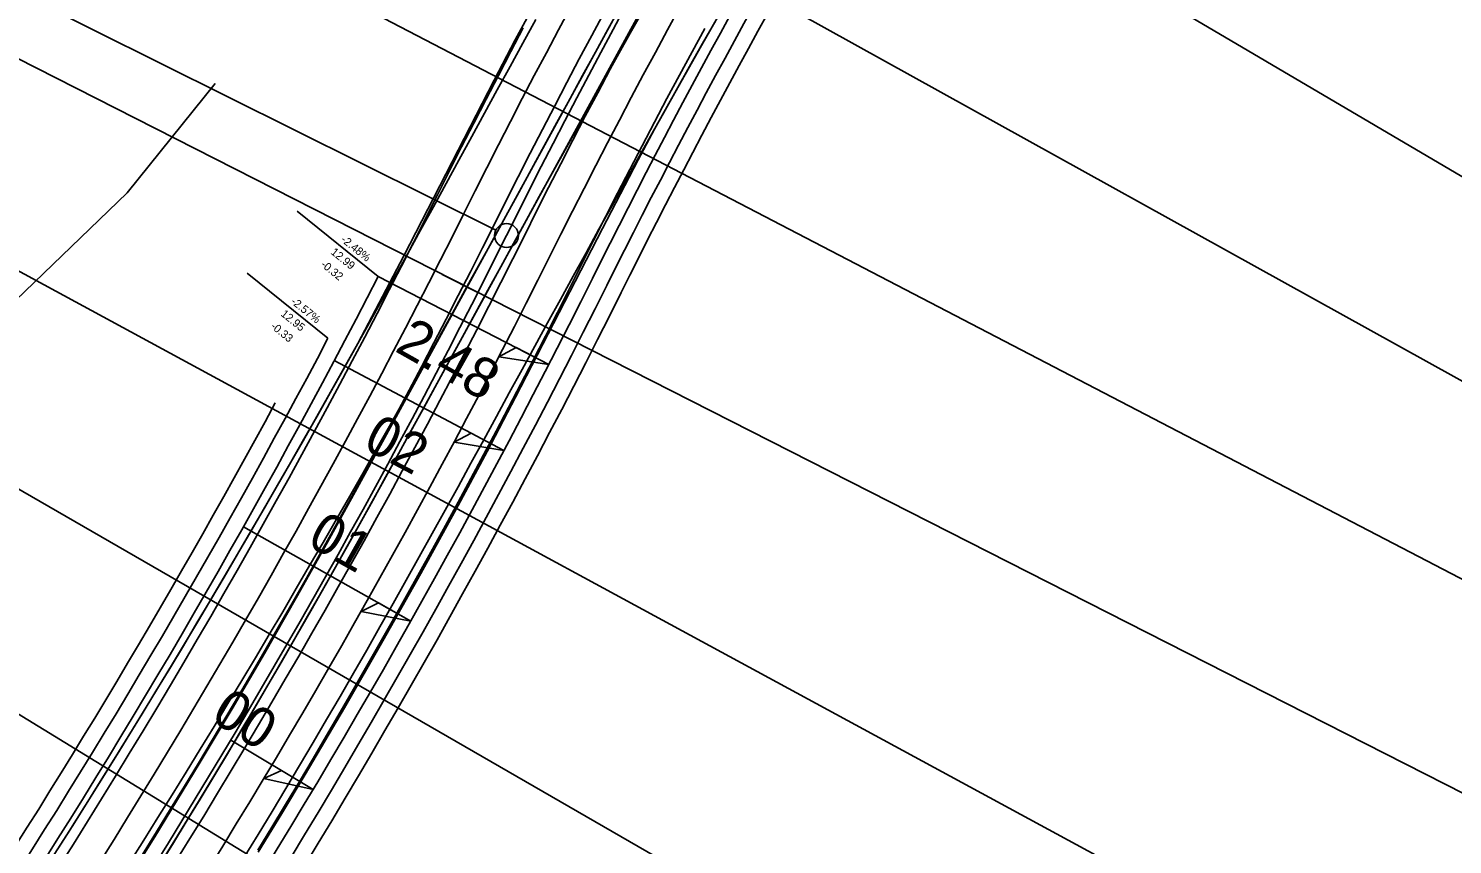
# Model space of a CAD drawing. Extents: x 2293233 to 2294507, y 892788 to 894229.
# Drawn here: x 2294121.5 to 2294299.4, y 893806.4 to 893908.4 of the extents above; entities that cross this region are included whole.
import ezdxf

# ---------------------------------------------------------------- set-up
doc = ezdxf.new("R2010")
doc.units = 0
for name, color, linetype in [('COGO Default Curve', 7, 'Continuous'), ('Default', 7, 'Continuous'), ('Prop EOT', 7, 'Continuous'), ('Prop Horizontal Alignment', 7, 'Continuous'), ('Prop Paved Shoulder', 7, 'Continuous'), ('Prop Superelevation  Arrow CELL', 7, 'Continuous'), ('Prop Superelevation Label', 7, 'Continuous'), ('Scratch_Level_0', 7, 'Continuous'), ('Scratch_Level_4', 7, 'Continuous'), ('Scratch_Level_5', 7, 'Continuous'), ('Scratch_Level_6', 7, 'Continuous')]:
    doc.layers.add(name, color=color, linetype=linetype)

msp = doc.modelspace()

# ---------------------------------------------------------------- linework, layer by layer
at = {"layer": 'COGO Default Curve'}
for points in [[(2294256.78, 894009.93), (2294251.82, 894002.81), (2294246.93, 893995.66), (2294242.09, 893988.47), (2294237.32, 893981.23), (2294233.33, 893975.08), (2294229.56, 893969.18), (2294225.66, 893962.97), (2294221.98, 893957.01), (2294218.17, 893950.75), (2294214.57, 893944.74), (2294211.02, 893938.7), (2294207.35, 893932.35), (2294201.43, 893921.91), (2294194.8, 893909.96), (2294162.57, 893850.95), (2294158.86, 893844.23), (2294154.94, 893837.24), (2294150.96, 893830.3), (2294146.92, 893823.38), (2294142.82, 893816.51), (2294137.26, 893807.39), (2294131.61, 893798.35)], [(2294136.62, 893801.84), (2294139.78, 893806.94), (2294142.73, 893811.78), (2294147.54, 893819.78), (2294152.1, 893827.54), (2294156.76, 893835.63), (2294161.67, 893844.34), (2294165.88, 893851.92), (2294170.85, 893860.96), (2294201.32, 893916.77)], [(2294209.54, 893913.24), (2294205.58, 893906.3), (2294201.5, 893899.05), (2294199.71, 893895.86), (2294197.69, 893892.02), (2294193.22, 893883.43), (2294182.36, 893862.34), (2294178.79, 893855.55), (2294175.16, 893848.78), (2294170.51, 893840.3), (2294165.77, 893831.88), (2294160.96, 893823.5), (2294156.06, 893815.17), (2294153.14, 893810.31), (2294150.2, 893805.46)], [(2294123.12, 893802.7), (2294126.34, 893807.75), (2294129.72, 893813.11), (2294132.88, 893818.2), (2294136.2, 893823.6), (2294139.48, 893829.01), (2294142.73, 893834.44), (2294149.15, 893845.34), (2294155.79, 893856.89), (2294162.65, 893869.06), (2294168.37, 893880.01), (2294179.69, 893901.98), (2294182.32, 893907.01), (2294184.99, 893912.02)], [(2294195.53, 893911.29), (2294193.93, 893908.37), (2294192.33, 893905.45), (2294190.73, 893902.53), (2294189.13, 893899.61), (2294187.53, 893896.68), (2294185.94, 893893.76), (2294184.34, 893890.83), (2294182.74, 893887.91), (2294181.14, 893884.98), (2294179.54, 893882.05), (2294177.93, 893879.13), (2294176.32, 893876.2), (2294174.71, 893873.28), (2294173.1, 893870.36), (2294171.47, 893867.44), (2294169.85, 893864.52), (2294168.22, 893861.61), (2294166.58, 893858.7), (2294164.94, 893855.79), (2294163.29, 893852.88), (2294161.63, 893849.98), (2294159.97, 893847.08), (2294158.3, 893844.18), (2294156.62, 893841.29), (2294154.94, 893838.41), (2294153.25, 893835.52), (2294151.55, 893832.65), (2294149.84, 893829.77), (2294148.13, 893826.9), (2294146.41, 893824.04), (2294144.67, 893821.18), (2294142.94, 893818.32), (2294141.19, 893815.47), (2294139.43, 893812.63), (2294137.66, 893809.79), (2294135.89, 893806.96), (2294134.11, 893804.13)], [(2294184.87, 893909.54), (2294183.27, 893906.61), (2294181.67, 893903.68), (2294180.07, 893900.76), (2294178.48, 893897.83), (2294176.88, 893894.91), (2294175.28, 893891.98), (2294173.68, 893889.06), (2294172.08, 893886.14), (2294170.48, 893883.22), (2294168.88, 893880.3), (2294167.27, 893877.39), (2294165.66, 893874.48), (2294164.05, 893871.57), (2294162.43, 893868.67), (2294160.8, 893865.76), (2294159.17, 893862.87), (2294157.54, 893859.97), (2294155.9, 893857.08), (2294154.25, 893854.2), (2294152.6, 893851.32), (2294150.94, 893848.44), (2294149.28, 893845.57), (2294147.6, 893842.7), (2294145.92, 893839.83), (2294144.24, 893836.97), (2294142.54, 893834.12), (2294140.84, 893831.27), (2294139.13, 893828.43), (2294137.41, 893825.59), (2294135.68, 893822.76), (2294133.95, 893819.93), (2294132.2, 893817.1), (2294130.45, 893814.29), (2294128.69, 893811.48), (2294126.92, 893808.67), (2294125.15, 893805.87)], [(2294193.45, 893910.49), (2294191.88, 893907.56), (2294190.32, 893904.63), (2294188.78, 893901.69), (2294187.24, 893898.75), (2294185.71, 893895.81), (2294184.19, 893892.86), (2294182.68, 893889.9), (2294181.19, 893886.94), (2294179.7, 893883.97), (2294178.21, 893880.99), (2294176.71, 893878.02), (2294175.2, 893875.05), (2294173.68, 893872.08), (2294172.15, 893869.11), (2294170.6, 893866.15), (2294169.05, 893863.2), (2294167.48, 893860.25), (2294165.9, 893857.3), (2294164.32, 893854.36), (2294162.72, 893851.42), (2294161.11, 893848.49), (2294159.49, 893845.56), (2294157.86, 893842.64), (2294156.21, 893839.72), (2294154.56, 893836.81), (2294152.9, 893833.91), (2294151.23, 893831.01), (2294149.55, 893828.11), (2294147.85, 893825.23), (2294146.15, 893822.34), (2294144.44, 893819.47), (2294142.71, 893816.6), (2294140.98, 893813.73), (2294139.24, 893810.88), (2294137.48, 893808.02), (2294135.72, 893805.18)], [(2294137.72, 893803.61), (2294139.46, 893806.43), (2294141.2, 893809.26), (2294142.92, 893812.09), (2294144.63, 893814.92), (2294146.34, 893817.77), (2294148.03, 893820.61), (2294149.72, 893823.47), (2294151.39, 893826.33), (2294153.06, 893829.19), (2294154.72, 893832.07), (2294156.37, 893834.95), (2294158.01, 893837.83), (2294159.64, 893840.72), (2294161.26, 893843.62), (2294162.88, 893846.52), (2294164.5, 893849.43), (2294166.11, 893852.34), (2294167.71, 893855.25), (2294169.32, 893858.17), (2294170.92, 893861.09), (2294172.51, 893864.01), (2294174.11, 893866.93), (2294175.71, 893869.86), (2294177.31, 893872.78), (2294178.9, 893875.71), (2294180.5, 893878.64), (2294182.1, 893881.56), (2294183.71, 893884.49), (2294185.32, 893887.42), (2294186.93, 893890.34), (2294188.54, 893893.26), (2294190.16, 893896.18), (2294191.78, 893899.1), (2294193.41, 893902.02), (2294195.05, 893904.93), (2294196.69, 893907.84), (2294198.33, 893910.75)], [(2294139.9, 893804.33), (2294141.65, 893807.15), (2294143.38, 893809.98), (2294145.11, 893812.82), (2294146.82, 893815.66), (2294148.53, 893818.51), (2294150.22, 893821.36), (2294151.91, 893824.22), (2294153.58, 893827.09), (2294155.25, 893829.96), (2294156.9, 893832.84), (2294158.55, 893835.72), (2294160.18, 893838.61), (2294161.81, 893841.5), (2294163.42, 893844.4), (2294165.02, 893847.31), (2294166.62, 893850.22), (2294168.2, 893853.13), (2294169.78, 893856.06), (2294171.34, 893858.98), (2294172.9, 893861.92), (2294174.44, 893864.85), (2294175.97, 893867.8), (2294177.5, 893870.75), (2294179.01, 893873.7), (2294180.51, 893876.66), (2294182, 893879.63), (2294183.49, 893882.6), (2294184.98, 893885.57), (2294186.48, 893888.55), (2294188, 893891.52), (2294189.53, 893894.48), (2294191.07, 893897.45), (2294192.62, 893900.4), (2294194.18, 893903.36), (2294195.75, 893906.31), (2294197.33, 893909.25)], [(2294148.45, 893804.82), (2294150.19, 893807.68), (2294151.92, 893810.54), (2294153.64, 893813.41), (2294155.35, 893816.28), (2294157.05, 893819.16), (2294158.74, 893822.04), (2294160.42, 893824.93), (2294162.09, 893827.83), (2294163.75, 893830.73), (2294165.4, 893833.64), (2294167.05, 893836.55), (2294168.68, 893839.47), (2294170.31, 893842.38), (2294171.93, 893845.3), (2294173.55, 893848.23), (2294175.16, 893851.15), (2294176.77, 893854.08), (2294178.37, 893857.01), (2294179.97, 893859.93), (2294181.57, 893862.86), (2294183.17, 893865.79), (2294184.77, 893868.71), (2294186.36, 893871.64), (2294187.96, 893874.56), (2294189.56, 893877.48), (2294191.16, 893880.4), (2294192.76, 893883.32), (2294194.37, 893886.23), (2294195.98, 893889.15), (2294197.59, 893892.06), (2294199.21, 893894.96), (2294200.83, 893897.86), (2294202.46, 893900.76), (2294204.09, 893903.66), (2294205.72, 893906.55), (2294207.37, 893909.44)], [(2294183.32, 893908.49), (2294181.75, 893905.53), (2294180.2, 893902.56), (2294178.66, 893899.59), (2294177.13, 893896.61), (2294175.61, 893893.63), (2294174.1, 893890.65), (2294172.6, 893887.65), (2294171.11, 893884.66), (2294169.6, 893881.68), (2294168.09, 893878.71), (2294166.57, 893875.75), (2294165.04, 893872.79), (2294163.5, 893869.84), (2294161.95, 893866.89), (2294160.39, 893863.95), (2294158.82, 893861.02), (2294157.24, 893858.1), (2294155.66, 893855.18), (2294154.06, 893852.27), (2294152.45, 893849.36), (2294150.83, 893846.46), (2294149.2, 893843.56), (2294147.56, 893840.67), (2294145.91, 893837.79), (2294144.25, 893834.92), (2294142.58, 893832.04), (2294140.9, 893829.18), (2294139.21, 893826.32), (2294137.51, 893823.47), (2294135.8, 893820.62), (2294134.08, 893817.78), (2294132.35, 893814.95), (2294130.61, 893812.12), (2294128.86, 893809.3), (2294127.1, 893806.48), (2294125.33, 893803.67)], [(2294150.14, 893805.71), (2294151.88, 893808.57), (2294153.61, 893811.43), (2294155.33, 893814.3), (2294157.04, 893817.18), (2294158.74, 893820.06), (2294160.43, 893822.95), (2294162.11, 893825.85), (2294163.78, 893828.75), (2294165.44, 893831.66), (2294167.09, 893834.57), (2294168.72, 893837.49), (2294170.35, 893840.41), (2294171.97, 893843.34), (2294173.58, 893846.28), (2294175.18, 893849.22), (2294176.77, 893852.16), (2294178.34, 893855.11), (2294179.91, 893858.07), (2294181.47, 893861.03), (2294183.01, 893864), (2294184.55, 893866.98), (2294186.08, 893869.96), (2294187.59, 893872.94), (2294189.1, 893875.93), (2294190.59, 893878.92), (2294192.09, 893881.91), (2294193.6, 893884.88), (2294195.11, 893887.85), (2294196.64, 893890.81), (2294198.17, 893893.77), (2294199.72, 893896.72), (2294201.27, 893899.66), (2294202.83, 893902.59), (2294204.41, 893905.52), (2294205.99, 893908.44)]]:
    msp.add_lwpolyline(points, dxfattribs=at)
msp.add_circle((2294175.85, 893885.22), 0.0417, dxfattribs=at)
msp.add_circle((2294175.85, 893885.22), 0.0417, dxfattribs=at)
for centre, radius, start, end in [((2295031.56, 893458.96), 956, 141.09608, 153.52096), ((2295031.56, 893458.96), 944, 141.09608, 153.52096), ((2293330.88, 894306.12), 944, 321.09608, 333.52096), ((2293330.88, 894306.12), 956, 321.09608, 333.52096)]:
    msp.add_arc(centre, radius, start, end, dxfattribs=at)
at = {"layer": 'Default'}
for p, q in [((2294155.07, 893885.57), (2294165.18, 893877.41)), ((2294148.83, 893877.83), (2294158.91, 893869.7))]:
    msp.add_line(p, q, dxfattribs=at)
at = {"layer": 'Prop EOT'}
for centre, radius, start, end in [((2295031.56, 893458.96), 938, 143.86429, 153.52096), ((2293330.88, 894306.12), 938, 321.09608, 332.80359), ((2293330.88, 894306.12), 962, 321.09608, 333.52096), ((2293330.88, 894306.12), 962, 321.09608, 333.52096)]:
    msp.add_arc(centre, radius, start, end, dxfattribs=at)
at = {"layer": 'Prop Horizontal Alignment'}
for p, q in [((2294179.88, 893883.21), (2293935.07, 894005.15)), ((2294177.64, 893875.42), (2294173.18, 893877.69))]:
    msp.add_line(p, q, dxfattribs=at)
msp.add_circle((2294181.22, 893882.54), 1.5, dxfattribs=at)
for centre, start, end in [((2295031.56, 893458.96), 141.09608, 153.52096), ((2295031.56, 893458.96), 141.09608, 153.52096), ((2293330.88, 894306.12), 321.09608, 333.52096), ((2293330.88, 894306.12), 321.09608, 333.52096)]:
    msp.add_arc(centre, 950, start, end, dxfattribs=at)
at = {"layer": 'Prop Paved Shoulder'}
for centre, radius, start, end in [((2295031.56, 893458.96), 936, 143.86429, 153.52096), ((2293330.88, 894306.12), 964, 321.09608, 333.52096), ((2293330.88, 894306.12), 936, 321.09608, 332.20827)]:
    msp.add_arc(centre, radius, start, end, dxfattribs=at)
at = {"layer": 'Prop Superelevation  Arrow CELL'}
for p, q in [((2294186.52, 893866.44), (2294165.18, 893877.41)), ((2294180.9, 893855.67), (2294159.7, 893866.91)), ((2294169.25, 893834.34), (2294148.34, 893846.11)), ((2294157.07, 893813.31), (2294146.76, 893819.46))]:
    msp.add_line(p, q, dxfattribs=at)
for points in [[(2294186.52, 893866.44), (2294180.27, 893867.4), (2294182.41, 893868.55)], [(2294180.9, 893855.67), (2294174.66, 893856.71), (2294176.82, 893857.83)], [(2294169.25, 893834.34), (2294163.04, 893835.54), (2294165.22, 893836.61)], [(2294157.07, 893813.31), (2294150.89, 893814.67), (2294153.1, 893815.68)]]:
    msp.add_lwpolyline(points, close=True, dxfattribs=at)
at = {"layer": 'Scratch_Level_0'}
for q in [(2294144.82, 893901.53), (2294115.87, 893870.59)]:
    msp.add_line((2294133.8, 893887.87), q, dxfattribs=at)
at = {"layer": 'Scratch_Level_4'}
for p, q in [((2294083.99, 894017.62), (2294342.42, 893865.26)), ((2294069.61, 893992.49), (2294331.96, 893846.98)), ((2294055.91, 893966.99), (2294322, 893828.44)), ((2294043.94, 893943.43), (2294311.34, 893807.42)), ((2294034.15, 893924.79), (2294297.88, 893781.79)), ((2294023.87, 893906.42), (2294283.75, 893756.53)), ((2294013.12, 893888.32), (2294268.96, 893731.65))]:
    msp.add_line(p, q, dxfattribs=at)
at = {"layer": 'Scratch_Level_5'}
for centre, radius, start, end in [((2295031.56, 893458.96), 934, 143.86429, 153.52096), ((2293330.88, 894306.12), 966, 321.09608, 333.52096), ((2293330.88, 894306.12), 934, 321.09608, 331.58156)]:
    msp.add_arc(centre, radius, start, end, dxfattribs=at)
at = {"layer": 'Scratch_Level_6'}
for p, q in [((2294155.07, 893885.57), (2294165.18, 893877.41)), ((2294148.83, 893877.83), (2294158.91, 893869.7))]:
    msp.add_line(p, q, dxfattribs=at)

# ---------------------------------------------------------------- texts
at = {"layer": 'Default'}
for s, p in [('12.99', (2294159.18, 893880.32)), ('-2.48%', (2294160.44, 893881.88)), ('-0.32', (2294157.93, 893878.77)), ('-2.57%', (2294154.18, 893874.15)), ('12.95', (2294152.93, 893872.6)), ('-0.33', (2294151.67, 893871.04))]:
    msp.add_text(s, height=1, rotation=321.0961, dxfattribs=at).set_placement(p)
at = {"layer": 'Prop Superelevation Label'}
for s, rotation, p in [('2.48', 330.586, (2294167.11, 893868.16)), ('02', 332.0797, (2294163.1, 893856.01)), ('01', 330.6323, (2294156.12, 893843.91)), ('00', 147.7373, (2294153.07, 893822.27))]:
    msp.add_text(s, height=5, rotation=rotation, dxfattribs=at).set_placement(p)

doc.saveas('drawing.dxf')
